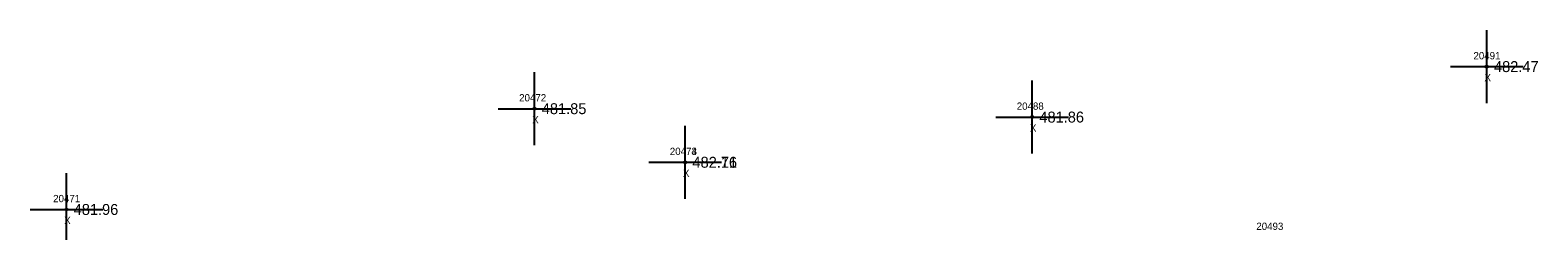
# Model space of a CAD drawing. Extents: x 1649406 to 1650436, y 896752 to 898178.
# Drawn here: x 1650210.9 to 1650418.5, y 897580 to 897607.5 of the extents above; entities that cross this region are included whole.
import ezdxf

# ---------------------------------------------------------------- set-up
doc = ezdxf.new("R2010")
doc.units = 0
for name, color, linetype in [('RD_EX_H2O_txCode', 7, 'Continuous'), ('RD_EX_Misc', 7, 'Continuous'), ('RD_EX_Misc_txCode', 7, 'Continuous'), ('RD_EX_TX_Misc_ELEV', 7, 'Continuous'), ('RD_SMD_Locator', 7, 'Continuous')]:
    doc.layers.add(name, color=color, linetype=linetype)

msp = doc.modelspace()

# ---------------------------------------------------------------- linework, layer by layer
at = {"layer": 'RD_EX_Misc'}
for p, q in [((1650411.45, 897597.53), (1650411.45, 897607.53)), ((1650280.37, 897591.75), (1650280.37, 897601.75)), ((1650348.87, 897590.6), (1650348.87, 897600.6)), ((1650406.45, 897602.53), (1650416.45, 897602.53)), ((1650275.37, 897596.75), (1650285.37, 897596.75)), ((1650301.11, 897584.39), (1650301.11, 897594.39)), ((1650301.11, 897584.39), (1650301.11, 897594.39)), ((1650343.87, 897595.6), (1650353.87, 897595.6)), ((1650296.11, 897589.39), (1650306.11, 897589.39)), ((1650296.11, 897589.39), (1650306.11, 897589.39)), ((1650215.93, 897577.91), (1650215.93, 897587.91)), ((1650210.93, 897582.91), (1650220.93, 897582.91))]:
    msp.add_line(p, q, dxfattribs=at)
at = {"layer": 'RD_SMD_Locator'}
for centre in [(1650411.45, 897602.53), (1650280.37, 897596.75), (1650348.87, 897595.6), (1650301.11, 897589.39), (1650301.11, 897589.39), (1650215.93, 897582.91)]:
    msp.add_circle(centre, 0.15, dxfattribs=at)

# ---------------------------------------------------------------- texts
at = {"layer": 'RD_EX_H2O_txCode'}
msp.add_text('20493', height=1, dxfattribs=at).set_placement((1650379.73, 897580.1))
at = {"layer": 'RD_EX_Misc_txCode'}
for s, p in [('20491', (1650409.62, 897603.53)), ('X', (1650411.14, 897600.53)), ('20472', (1650278.25, 897597.75)), ('20488', (1650346.75, 897596.6)), ('X', (1650280.05, 897594.75)), ('X', (1650348.56, 897593.6)), ('20473', (1650298.99, 897590.39)), ('20474', (1650298.99, 897590.39)), ('X', (1650300.8, 897587.39)), ('X', (1650300.8, 897587.39)), ('20471', (1650214.1, 897583.91)), ('X', (1650215.62, 897580.91))]:
    msp.add_text(s, height=1, dxfattribs=at).set_placement(p)
at = {"layer": 'RD_EX_TX_Misc_ELEV'}
for s, p in [('482.47', (1650412.45, 897601.78)), ('481.85', (1650281.37, 897596)), ('481.86', (1650349.87, 897594.85)), ('482.11', (1650302.11, 897588.64)), ('482.76', (1650302.11, 897588.64)), ('481.96', (1650216.93, 897582.16))]:
    msp.add_text(s, height=1.5, dxfattribs=at).set_placement(p)

doc.saveas('drawing.dxf')
